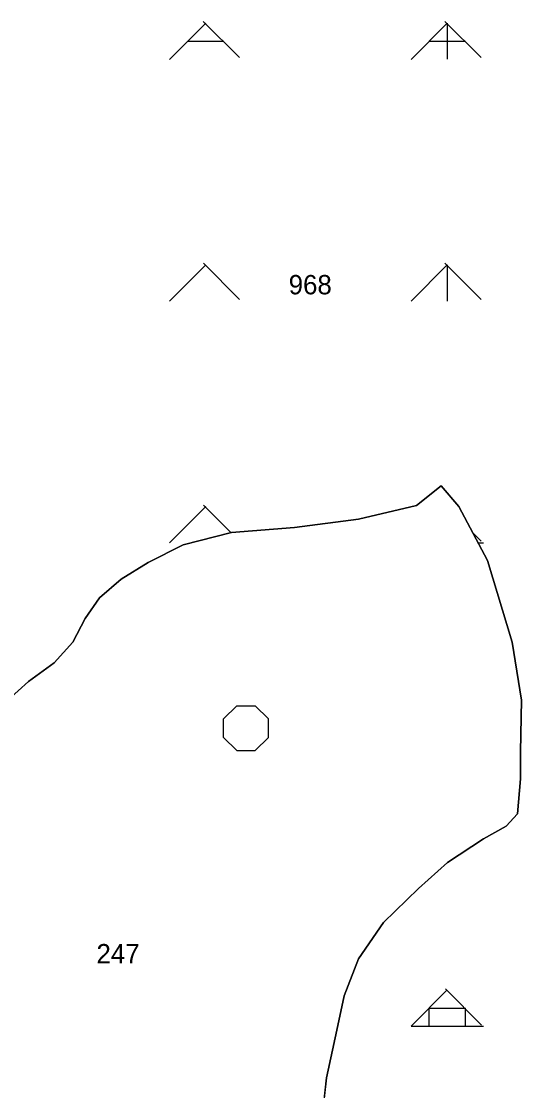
# Model space of a CAD drawing. Extents: x 410727 to 412947, y 4463506 to 4466382.
# Drawn here: x 412074.5 to 412178, y 4465822.5 to 4466043.7 of the extents above; entities that cross this region are included whole.
import ezdxf

# ---------------------------------------------------------------- set-up
doc = ezdxf.new("R2010")
doc.units = 0
for name, color, linetype in [('ADAKENARI', 7, 'Continuous'), ('KDS_PARSEL_NO', 7, 'Continuous'), ('KDS_PL', 7, 'Continuous'), ('PL_AYA_ORMAN', 7, 'Continuous'), ('PL_KA_TARIM_DIGER', 7, 'Continuous'), ('TR_ORMAN', 7, 'Continuous'), ('TR_TARIMALANI', 7, 'Continuous')]:
    doc.layers.add(name, color=color, linetype=linetype)

msp = doc.modelspace()

# ---------------------------------------------------------------- linework, layer by layer
at = {"layer": 'ADAKENARI'}
for p, q in [((412161.39, 4465947.6), (412156.26, 4465943.54)), ((412165.02, 4465943.32), (412161.39, 4465947.6)), ((412156.26, 4465943.54), (412144.3, 4465940.75)), ((412171, 4465932.19), (412165.02, 4465943.32)), ((412144.3, 4465940.75), (412131.06, 4465939.04)), ((412131.06, 4465939.04), (412118.03, 4465937.97)), ((412118.03, 4465937.97), (412108, 4465935.4)), ((412108, 4465935.4), (412100.73, 4465931.76)), ((412176.12, 4465915.29), (412171, 4465932.19)), ((412100.73, 4465931.76), (412095.18, 4465928.34)), ((412095.18, 4465928.34), (412090.7, 4465924.49)), ((412090.7, 4465924.49), (412087.71, 4465920.21)), ((412087.71, 4465920.21), (412085.15, 4465915.29)), ((412085.15, 4465915.29), (412081.3, 4465911.01)), ((412178.04, 4465903.31), (412176.12, 4465915.29)), ((412081.3, 4465911.01), (412075.96, 4465907.16)), ((412075.96, 4465907.16), (412071.69, 4465903.31)), ((412177.83, 4465892.61), (412178.04, 4465903.31)), ((412177.83, 4465887.04), (412177.83, 4465892.61)), ((412177.83, 4465887.04), (412177.83, 4465892.61)), ((412177.19, 4465879.77), (412177.83, 4465887.04)), ((412174.84, 4465877.2), (412177.19, 4465879.77)), ((412170.14, 4465874.63), (412174.84, 4465877.2)), ((412170.14, 4465874.63), (412174.84, 4465877.2)), ((412162.67, 4465869.71), (412170.14, 4465874.63)), ((412156.69, 4465864.36), (412162.67, 4465869.71)), ((412149.43, 4465857.3), (412156.69, 4465864.36)), ((412144.3, 4465849.81), (412149.43, 4465857.3)), ((412141.31, 4465842.11), (412144.3, 4465849.81)), ((412139.82, 4465835.05), (412141.31, 4465842.11)), ((412137.68, 4465825.2), (412139.82, 4465835.05)), ((412135.76, 4465808.08), (412137.68, 4465825.2))]:
    msp.add_line(p, q, dxfattribs=at)
at = {"layer": 'KDS_PL'}
for p, q in [((412161.39, 4465947.6), (412156.26, 4465943.54)), ((412165.02, 4465943.32), (412161.39, 4465947.6)), ((412156.26, 4465943.54), (412144.3, 4465940.75)), ((412171, 4465932.19), (412165.02, 4465943.32)), ((412144.3, 4465940.75), (412131.06, 4465939.04)), ((412131.06, 4465939.04), (412118.03, 4465937.97)), ((412118.03, 4465937.97), (412108, 4465935.4)), ((412108, 4465935.4), (412100.73, 4465931.76)), ((412176.12, 4465915.29), (412171, 4465932.19)), ((412100.73, 4465931.76), (412095.18, 4465928.34)), ((412095.18, 4465928.34), (412090.7, 4465924.49)), ((412090.7, 4465924.49), (412087.71, 4465920.21)), ((412087.71, 4465920.21), (412085.15, 4465915.29)), ((412085.15, 4465915.29), (412081.3, 4465911.01)), ((412178.04, 4465903.31), (412176.12, 4465915.29)), ((412081.3, 4465911.01), (412075.96, 4465907.16)), ((412075.96, 4465907.16), (412071.69, 4465903.31)), ((412177.83, 4465892.61), (412178.04, 4465903.31)), ((412177.83, 4465887.04), (412177.83, 4465892.61)), ((412177.19, 4465879.77), (412177.83, 4465887.04)), ((412174.84, 4465877.2), (412177.19, 4465879.77)), ((412170.14, 4465874.63), (412174.84, 4465877.2)), ((412162.67, 4465869.71), (412170.14, 4465874.63)), ((412156.69, 4465864.36), (412162.67, 4465869.71)), ((412149.43, 4465857.3), (412156.69, 4465864.36)), ((412144.3, 4465849.81), (412149.43, 4465857.3)), ((412141.31, 4465842.11), (412144.3, 4465849.81)), ((412139.82, 4465835.05), (412141.31, 4465842.11)), ((412137.68, 4465825.2), (412139.82, 4465835.05)), ((412135.76, 4465808.08), (412137.68, 4465825.2))]:
    msp.add_line(p, q, dxfattribs=at)
at = {"layer": 'PL_AYA_ORMAN'}
msp.add_lwpolyline([(412071.69, 4465903.31), (412075.96, 4465907.16), (412081.3, 4465911.01), (412085.15, 4465915.29), (412087.71, 4465920.21), (412090.7, 4465924.49), (412095.18, 4465928.34), (412100.73, 4465931.76), (412108, 4465935.4), (412118.03, 4465937.97), (412131.06, 4465939.04), (412144.3, 4465940.75), (412156.26, 4465943.54), (412161.39, 4465947.6), (412165.02, 4465943.32), (412171, 4465932.19), (412176.12, 4465915.29), (412178.04, 4465903.31), (412177.83, 4465892.61), (412177.83, 4465887.04), (412177.19, 4465879.77), (412174.84, 4465877.2), (412170.14, 4465874.63), (412162.67, 4465869.71), (412156.69, 4465864.36), (412149.43, 4465857.3), (412144.3, 4465849.81), (412141.31, 4465842.11), (412139.82, 4465835.05), (412137.68, 4465825.2), (412135.76, 4465808.08)], dxfattribs=at)
at = {"layer": 'PL_KA_TARIM_DIGER'}
msp.add_lwpolyline([(412071.69, 4465903.31), (412075.96, 4465907.16), (412081.3, 4465911.01), (412085.15, 4465915.29), (412087.71, 4465920.21), (412090.7, 4465924.49), (412095.18, 4465928.34), (412100.73, 4465931.76), (412108, 4465935.4), (412118.03, 4465937.97), (412131.06, 4465939.04), (412144.3, 4465940.75), (412156.26, 4465943.54), (412161.39, 4465947.6), (412165.02, 4465943.32), (412171, 4465932.19), (412176.12, 4465915.29), (412178.04, 4465903.31), (412177.83, 4465892.61), (412177.83, 4465887.04), (412177.19, 4465879.77), (412174.84, 4465877.2), (412170.14, 4465874.63), (412162.67, 4465869.71), (412156.69, 4465864.36), (412149.43, 4465857.3), (412144.3, 4465849.81), (412141.31, 4465842.11), (412139.82, 4465835.05), (412137.68, 4465825.2), (412135.76, 4465808.08)], dxfattribs=at)
at = {"layer": 'TR_ORMAN'}
for p, q in [((412105.16, 4466035.83), (412112.66, 4466043.32)), ((412105.16, 4466035.83), (412112.66, 4466043.32)), ((412119.65, 4466036.2), (412112.15, 4466043.7)), ((412119.65, 4466036.2), (412112.15, 4466043.7)), ((412155.16, 4466035.83), (412162.66, 4466043.33)), ((412169.64, 4466036.2), (412162.14, 4466043.7)), ((412169.64, 4466036.2), (412162.14, 4466043.7)), ((412162.67, 4466035.86), (412162.67, 4466043.36)), ((412108.92, 4466039.61), (412116.42, 4466039.61)), ((412158.92, 4466039.61), (412166.42, 4466039.61)), ((412105.16, 4465985.83), (412112.66, 4465993.33)), ((412119.68, 4465986.18), (412112.18, 4465993.68)), ((412119.68, 4465986.18), (412112.18, 4465993.68)), ((412155.16, 4465985.84), (412162.66, 4465993.34)), ((412155.16, 4465985.84), (412162.66, 4465993.34)), ((412169.67, 4465986.18), (412162.17, 4465993.68)), ((412169.67, 4465986.18), (412162.17, 4465993.68)), ((412162.67, 4465985.86), (412162.67, 4465993.36)), ((412105.16, 4465935.84), (412112.66, 4465943.34)), ((412105.16, 4465935.84), (412112.66, 4465943.34)), ((412117.92, 4465937.94), (412112.21, 4465943.65)), ((412117.92, 4465937.94), (412112.21, 4465943.65)), ((412169.7, 4465936.15), (412167.9, 4465937.95)), ((412169.03, 4465935.86), (412170.17, 4465935.86)), ((412169.77, 4465836.1), (412162.27, 4465843.6)), ((412155.16, 4465835.86), (412162.66, 4465843.36)), ((412158.92, 4465835.86), (412158.92, 4465839.61)), ((412158.92, 4465839.61), (412166.42, 4465839.61)), ((412166.42, 4465835.86), (412166.42, 4465839.61)), ((412155.17, 4465835.86), (412170.17, 4465835.86))]:
    msp.add_line(p, q, dxfattribs=at)
at = {"layer": 'TR_TARIMALANI'}
for p, q in [((412116.37, 4465899.43), (412119.08, 4465902.14)), ((412119.08, 4465902.14), (412122.91, 4465902.14)), ((412125.62, 4465899.43), (412122.91, 4465902.14)), ((412116.37, 4465895.6), (412116.37, 4465899.43)), ((412116.37, 4465895.6), (412116.37, 4465899.43)), ((412125.62, 4465895.6), (412125.62, 4465899.43)), ((412119.08, 4465892.89), (412116.37, 4465895.6)), ((412122.91, 4465892.89), (412125.62, 4465895.6)), ((412119.08, 4465892.89), (412122.91, 4465892.89))]:
    msp.add_line(p, q, dxfattribs=at)

# ---------------------------------------------------------------- texts
at = {"layer": 'KDS_PARSEL_NO'}
for s, p in [('968', (412129.83, 4465987.24)), ('247', (412090.05, 4465848.85))]:
    msp.add_text(s, height=4, dxfattribs=at).set_placement(p)

doc.saveas('drawing.dxf')
